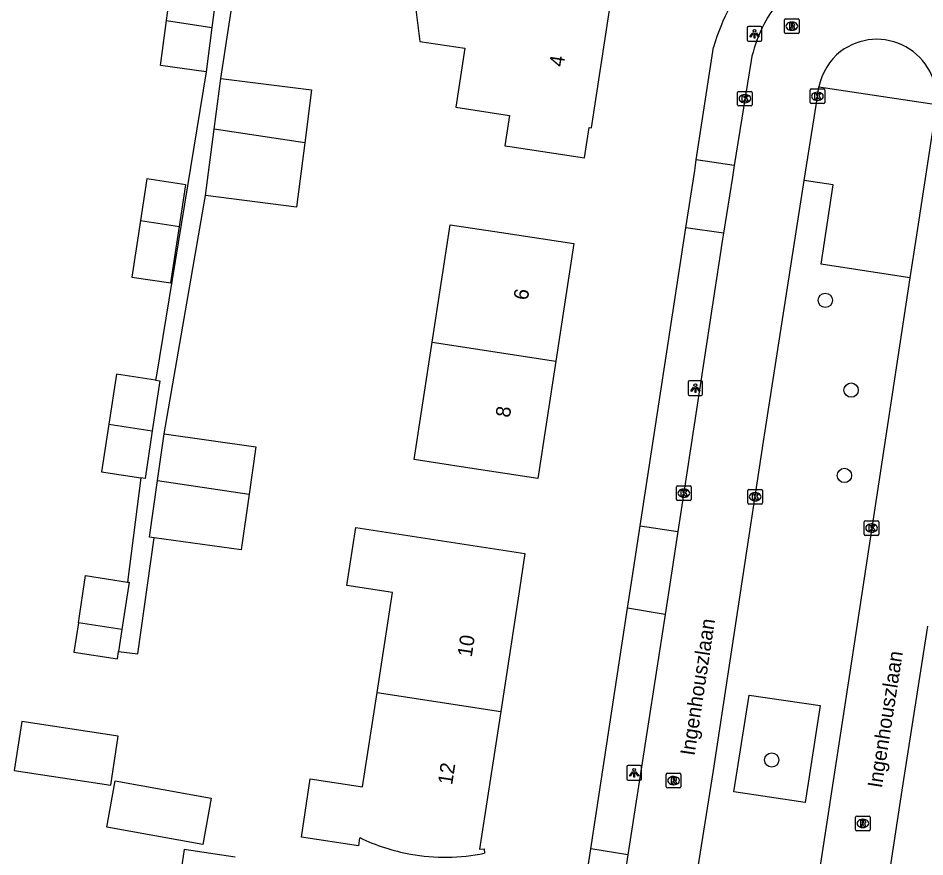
# Model space of a CAD drawing. Extents: x 161486 to 162249, y 379484 to 380829.
# Drawn here: x 162025.3 to 162087.4, y 380415.4 to 380472.8 of the extents above; entities that cross this region are included whole.
import ezdxf

# ---------------------------------------------------------------- set-up
doc = ezdxf.new("R2010")
doc.units = 0
for name, color, linetype in [('IMGEO_Boom', 7, 'Continuous'), ('IMGEO_Groenvoorziening', 7, 'Continuous'), ('IMGEO_Kolk', 7, 'Continuous'), ('IMGEO_Lichtpunt', 7, 'Continuous'), ('IMGEO_Openbare_ruimte_label', 7, 'Continuous'), ('IMGEO_Pand', 7, 'Continuous'), ('IMGEO_Pand_nummerreeks', 7, 'Continuous'), ('IMGEO_Rijbaan_lokaal_open', 7, 'Continuous'), ('IMGEO_Rioolput', 7, 'Continuous'), ('IMGEO_Voetpad_open', 7, 'Continuous')]:
    doc.layers.add(name, color=color, linetype=linetype)

msp = doc.modelspace()

# ---------------------------------------------------------------- linework, layer by layer
at = {"layer": 'IMGEO_Boom'}
for centre in [(162080.548, 380453.464), (162082.314, 380447.322), (162081.854, 380441.484), (162076.881, 380422.024)]:
    msp.add_circle(centre, 0.489, dxfattribs=at)
at = {"layer": 'IMGEO_Groenvoorziening'}
for points in [[(162086.334, 380454.996), (162080.254, 380455.927), (162081.091, 380461.363), (162079.109, 380461.669)], [(162074.286, 380419.839), (162075.344, 380426.462), (162080.192, 380425.742), (162079.172, 380419.106), (162074.286, 380419.839)]]:
    msp.add_lwpolyline(points, dxfattribs=at)
at = {"layer": 'IMGEO_Kolk'}
for p, q in [((162074.543, 380466.831), (162074.543, 380467.683)), ((162074.618, 380467.757), (162075.47, 380467.757)), ((162075.544, 380467.683), (162075.544, 380466.831)), ((162079.503, 380466.993), (162079.503, 380467.845)), ((162079.578, 380467.919), (162080.43, 380467.919)), ((162079.991, 380467.699), (162080.016, 380467.699)), ((162080.504, 380467.845), (162080.504, 380466.993)), ((162075.031, 380467.537), (162075.056, 380467.537)), ((162080.014, 380467.139), (162079.989, 380467.139)), ((162075.47, 380466.757), (162074.618, 380466.757)), ((162075.054, 380466.977), (162075.029, 380466.977)), ((162080.43, 380466.919), (162079.578, 380466.919)), ((162070.364, 380439.852), (162070.364, 380440.704)), ((162070.439, 380440.778), (162071.291, 380440.778)), ((162070.852, 380440.558), (162070.877, 380440.558)), ((162071.365, 380440.704), (162071.365, 380439.852)), ((162075.244, 380439.603), (162075.244, 380440.455)), ((162075.319, 380440.529), (162076.171, 380440.529)), ((162076.245, 380440.455), (162076.245, 380439.603)), ((162071.291, 380439.778), (162070.439, 380439.778)), ((162070.875, 380439.998), (162070.85, 380439.998)), ((162075.755, 380439.749), (162075.73, 380439.749)), ((162075.732, 380440.309), (162075.757, 380440.309)), ((162076.171, 380439.529), (162075.319, 380439.529)), ((162083.216, 380437.462), (162083.216, 380438.314)), ((162083.291, 380438.388), (162084.143, 380438.388)), ((162083.704, 380438.168), (162083.729, 380438.168)), ((162084.217, 380438.314), (162084.217, 380437.462)), ((162084.143, 380437.388), (162083.291, 380437.388)), ((162083.727, 380437.608), (162083.702, 380437.608))]:
    msp.add_line(p, q, dxfattribs=at)
for points in [[(162074.543, 380466.831), (162074.543, 380467.683)], [(162074.618, 380467.757), (162075.47, 380467.757)], [(162075.544, 380467.683), (162075.544, 380466.831)], [(162079.503, 380466.993), (162079.503, 380467.845)], [(162079.578, 380467.919), (162080.43, 380467.919)], [(162079.824, 380467.619), (162079.947, 380467.619), (162079.947, 380467.468), (162080.077, 380467.619), (162080.241, 380467.619), (162080.095, 380467.468), (162080.248, 380467.219), (162080.096, 380467.219), (162080.011, 380467.383), (162079.947, 380467.316), (162079.947, 380467.219), (162079.824, 380467.219), (162079.824, 380467.619)], [(162080.504, 380467.845), (162080.504, 380466.993)], [(162074.864, 380467.457), (162074.987, 380467.457), (162074.987, 380467.306), (162075.117, 380467.457), (162075.281, 380467.457), (162075.135, 380467.306), (162075.288, 380467.057), (162075.136, 380467.057), (162075.051, 380467.221), (162074.987, 380467.154), (162074.987, 380467.057), (162074.864, 380467.057), (162074.864, 380467.457)], [(162075.47, 380466.757), (162074.618, 380466.757)], [(162080.43, 380466.919), (162079.578, 380466.919)], [(162070.364, 380439.852), (162070.364, 380440.704)], [(162070.439, 380440.778), (162071.291, 380440.778)], [(162070.685, 380440.478), (162070.808, 380440.478), (162070.808, 380440.327), (162070.938, 380440.478), (162071.102, 380440.478), (162070.956, 380440.327), (162071.109, 380440.078), (162070.957, 380440.078), (162070.872, 380440.242), (162070.808, 380440.175), (162070.808, 380440.078), (162070.685, 380440.078), (162070.685, 380440.478)], [(162071.365, 380440.704), (162071.365, 380439.852)], [(162075.244, 380439.603), (162075.244, 380440.455)], [(162075.319, 380440.529), (162076.171, 380440.529)], [(162076.245, 380440.455), (162076.245, 380439.603)], [(162071.291, 380439.778), (162070.439, 380439.778)], [(162075.565, 380440.229), (162075.688, 380440.229), (162075.688, 380440.078), (162075.818, 380440.229), (162075.982, 380440.229), (162075.836, 380440.078), (162075.989, 380439.829), (162075.837, 380439.829), (162075.752, 380439.993), (162075.688, 380439.926), (162075.688, 380439.829), (162075.565, 380439.829), (162075.565, 380440.229)], [(162076.171, 380439.529), (162075.319, 380439.529)], [(162083.216, 380437.462), (162083.216, 380438.314)], [(162083.291, 380438.388), (162084.143, 380438.388)], [(162083.537, 380438.088), (162083.66, 380438.088), (162083.66, 380437.937), (162083.79, 380438.088), (162083.954, 380438.088), (162083.808, 380437.937), (162083.961, 380437.688), (162083.809, 380437.688), (162083.724, 380437.852), (162083.66, 380437.785), (162083.66, 380437.688), (162083.537, 380437.688), (162083.537, 380438.088)], [(162084.217, 380438.314), (162084.217, 380437.462)], [(162084.143, 380437.388), (162083.291, 380437.388)]]:
    msp.add_lwpolyline(points, dxfattribs=at)
for centre, start, end in [((162074.62, 380467.681), 91.55205, 178.44795), ((162074.62, 380467.681), 91.55205, 178.44795), ((162075.468, 380467.681), 1.55205, 88.44795), ((162075.468, 380467.681), 1.55205, 88.44795), ((162079.58, 380467.843), 91.55205, 178.44795), ((162079.58, 380467.843), 91.55205, 178.44795), ((162080.428, 380467.843), 1.55205, 88.44795), ((162080.428, 380467.843), 1.55205, 88.44795), ((162079.58, 380466.995), 181.55205, 268.44795), ((162079.58, 380466.995), 181.55205, 268.44795), ((162080.428, 380466.995), 271.55205, 358.44795), ((162080.428, 380466.995), 271.55205, 358.44795), ((162074.62, 380466.833), 181.55205, 268.44795), ((162074.62, 380466.833), 181.55205, 268.44795), ((162075.468, 380466.833), 271.55205, 358.44795), ((162075.468, 380466.833), 271.55205, 358.44795), ((162070.441, 380440.702), 91.55205, 178.44795), ((162070.441, 380440.702), 91.55205, 178.44795), ((162071.289, 380440.702), 1.55205, 88.44795), ((162071.289, 380440.702), 1.55205, 88.44795), ((162075.321, 380440.453), 91.55205, 178.44795), ((162075.321, 380440.453), 91.55205, 178.44795), ((162076.169, 380440.453), 1.55205, 88.44795), ((162076.169, 380440.453), 1.55205, 88.44795), ((162070.441, 380439.854), 181.55205, 268.44795), ((162070.441, 380439.854), 181.55205, 268.44795), ((162071.289, 380439.854), 271.55205, 358.44795), ((162071.289, 380439.854), 271.55205, 358.44795), ((162075.321, 380439.605), 181.55205, 268.44795), ((162075.321, 380439.605), 181.55205, 268.44795), ((162076.169, 380439.605), 271.55205, 358.44795), ((162076.169, 380439.605), 271.55205, 358.44795), ((162083.293, 380438.312), 91.55205, 178.44795), ((162083.293, 380438.312), 91.55205, 178.44795), ((162084.141, 380438.312), 1.55205, 88.44795), ((162084.141, 380438.312), 1.55205, 88.44795), ((162083.293, 380437.464), 181.55205, 268.44795), ((162083.293, 380437.464), 181.55205, 268.44795), ((162084.141, 380437.464), 271.55205, 358.44795), ((162084.141, 380437.464), 271.55205, 358.44795)]:
    msp.add_arc(centre, 0.0765, start, end, dxfattribs=at)
for centre, major_axis, ratio, start_param, end_param in [((162079.99, 380467.419), (-0.387, 0.002), 0.722429, 4.712389, 7.853982), ((162080.015, 380467.419), (-0.39, 0.002), 0.717154, 1.570796, 4.712389), ((162075.03, 380467.257), (-0.387, 0.002), 0.722429, 4.712389, 7.853982), ((162075.055, 380467.257), (-0.39, 0.002), 0.717154, 1.570796, 4.712389), ((162070.851, 380440.278), (-0.387, 0.002), 0.722429, 4.712389, 7.853982), ((162070.876, 380440.278), (-0.39, 0.002), 0.717154, 1.570796, 4.712389), ((162075.731, 380440.029), (-0.387, 0.002), 0.722429, 4.712389, 7.853982), ((162075.756, 380440.029), (-0.39, 0.002), 0.717154, 1.570796, 4.712389), ((162083.703, 380437.888), (-0.387, 0.002), 0.722429, 4.712389, 7.853982), ((162083.728, 380437.888), (-0.39, 0.002), 0.717154, 1.570796, 4.712389)]:
    msp.add_ellipse(centre, major_axis=major_axis, ratio=ratio, start_param=start_param, end_param=end_param, dxfattribs=at)
at = {"layer": 'IMGEO_Lichtpunt'}
for p, q in [((162075.203, 380472.098), (162075.203, 380471.291)), ((162075.203, 380472.098), (162075.203, 380471.291)), ((162076.105, 380472.193), (162075.297, 380472.193)), ((162076.105, 380472.193), (162075.297, 380472.193)), ((162076.199, 380471.291), (162076.199, 380472.098)), ((162076.199, 380471.291), (162076.199, 380472.098)), ((162075.297, 380471.197), (162076.105, 380471.197)), ((162075.297, 380471.197), (162076.105, 380471.197)), ((162071.154, 380447.864), (162071.154, 380447.057)), ((162071.154, 380447.864), (162071.154, 380447.057)), ((162072.056, 380447.959), (162071.248, 380447.959)), ((162072.056, 380447.959), (162071.248, 380447.959)), ((162072.15, 380447.057), (162072.15, 380447.864)), ((162072.15, 380447.057), (162072.15, 380447.864)), ((162071.248, 380446.963), (162072.056, 380446.963)), ((162071.248, 380446.963), (162072.056, 380446.963)), ((162066.967, 380421.548), (162066.967, 380420.741)), ((162066.967, 380421.548), (162066.967, 380420.741)), ((162067.869, 380421.643), (162067.061, 380421.643)), ((162067.869, 380421.643), (162067.061, 380421.643)), ((162067.963, 380420.741), (162067.963, 380421.548)), ((162067.963, 380420.741), (162067.963, 380421.548)), ((162067.061, 380420.647), (162067.869, 380420.647)), ((162067.061, 380420.647), (162067.869, 380420.647))]:
    msp.add_line(p, q, dxfattribs=at)
for points in [[(162075.577, 380471.762), (162075.616, 380471.734), (162075.428, 380471.472), (162075.39, 380471.499), (162075.577, 380471.762)], [(162075.679, 380471.714), (162075.726, 380471.714), (162075.726, 380471.392), (162075.679, 380471.392), (162075.679, 380471.714)], [(162075.789, 380471.734), (162075.827, 380471.761), (162076.014, 380471.499), (162075.975, 380471.471), (162075.789, 380471.734)], [(162071.528, 380447.528), (162071.567, 380447.5), (162071.379, 380447.238), (162071.341, 380447.265), (162071.528, 380447.528)], [(162071.63, 380447.48), (162071.677, 380447.48), (162071.677, 380447.158), (162071.63, 380447.158), (162071.63, 380447.48)], [(162071.74, 380447.5), (162071.778, 380447.527), (162071.965, 380447.265), (162071.926, 380447.237), (162071.74, 380447.5)], [(162067.341, 380421.212), (162067.38, 380421.184), (162067.192, 380420.922), (162067.154, 380420.949), (162067.341, 380421.212)], [(162067.443, 380421.164), (162067.49, 380421.164), (162067.49, 380420.842), (162067.443, 380420.842), (162067.443, 380421.164)], [(162067.553, 380421.184), (162067.591, 380421.211), (162067.778, 380420.949), (162067.739, 380420.921), (162067.553, 380421.184)]]:
    msp.add_lwpolyline(points, dxfattribs=at)
for centre in [(162075.702, 380471.896), (162071.653, 380447.662), (162067.466, 380421.346)]:
    msp.add_circle(centre, 0.0994, dxfattribs=at)
for centre, start, end in [((162075.297, 380472.098), 90, 180), ((162075.297, 380472.098), 90, 180), ((162076.105, 380472.098), 0, 90), ((162076.105, 380472.098), 0, 90), ((162075.297, 380471.291), 180, 270), ((162075.297, 380471.291), 180, 270), ((162076.105, 380471.291), 270, 0), ((162076.105, 380471.291), 270, 360), ((162071.248, 380447.864), 90, 180), ((162071.248, 380447.864), 90, 180), ((162072.056, 380447.864), 0, 90), ((162072.056, 380447.864), 0, 90), ((162071.248, 380447.057), 180, 270), ((162071.248, 380447.057), 180, 270), ((162072.056, 380447.057), 270, 0), ((162072.056, 380447.057), 270, 360), ((162067.061, 380421.548), 90, 180), ((162067.061, 380421.548), 90, 180), ((162067.869, 380421.548), 0, 90), ((162067.869, 380421.548), 0, 90), ((162067.061, 380420.741), 180, 270), ((162067.061, 380420.741), 180, 270), ((162067.869, 380420.741), 270, 0), ((162067.869, 380420.741), 270, 360)]:
    msp.add_arc(centre, 0.0946, start, end, dxfattribs=at)
at = {"layer": 'IMGEO_Pand'}
for points in [[(162035.461, 380472.596), (162035.933, 380476.135), (162039.053, 380475.719)], [(162039.053, 380475.719), (162038.574, 380472.119)], [(162057.421, 380474.6), (162053.993, 380475.125), (162052.273, 380475.388), (162052.804, 380471.178), (162055.87, 380470.71), (162055.254, 380466.675), (162058.941, 380466.112), (162058.624, 380464.037), (162059.118, 380463.961), (162064.06, 380463.205), (162064.377, 380465.279), (162064.545, 380465.254), (162065.78, 380473.32)], [(162038.171, 380469.102), (162035.05, 380469.518), (162035.461, 380472.596)], [(162035.461, 380472.596), (162038.574, 380472.119)], [(162038.574, 380472.119), (162038.171, 380469.102)], [(162038.733, 380465.178), (162039.182, 380468.642)], [(162039.182, 380468.642), (162045.384, 380467.857), (162044.927, 380464.247)], [(162038.142, 380460.624), (162038.733, 380465.178)], [(162044.927, 380464.247), (162038.733, 380465.178)], [(162044.927, 380464.247), (162044.369, 380459.836), (162038.142, 380460.624)], [(162036.345, 380458.507), (162036.782, 380461.361), (162034.119, 380461.768), (162033.682, 380458.914)], [(162033.682, 380458.914), (162033.092, 380455.057), (162035.754, 380454.65), (162036.345, 380458.507)], [(162033.682, 380458.914), (162036.345, 380458.507)], [(162053.641, 380450.606), (162054.871, 380458.639), (162058.393, 380458.1), (162063.335, 380457.343), (162062.105, 380449.31)], [(162062.105, 380449.31), (162060.875, 380441.275), (162055.933, 380442.032), (162052.41, 380442.571), (162053.641, 380450.606)], [(162053.641, 380450.606), (162062.105, 380449.31)], [(162034.717, 380448.001), (162032.039, 380448.411), (162031.515, 380444.987)], [(162034.717, 380448.001), (162035.018, 380447.955), (162034.494, 380444.531)], [(162031.515, 380444.987), (162031.017, 380441.736), (162033.708, 380441.324)], [(162031.515, 380444.987), (162034.494, 380444.531)], [(162034.494, 380444.531), (162033.997, 380441.28), (162033.708, 380441.324)], [(162034.847, 380441.152), (162035.293, 380444.33)], [(162035.293, 380444.33), (162041.567, 380443.449), (162041.112, 380440.21)], [(162034.627, 380437.222), (162034.302, 380437.268), (162034.847, 380441.152)], [(162034.847, 380441.152), (162041.112, 380440.21)], [(162041.112, 380440.21), (162040.576, 380436.387), (162034.627, 380437.222)], [(162049.873, 380426.629), (162050.922, 380433.478), (162047.805, 380433.956), (162048.412, 380437.923), (162059.989, 380436.151), (162059.567, 380433.393), (162058.333, 380425.335)], [(162029.434, 380431.396), (162029.93, 380434.632), (162032.806, 380434.192)], [(162032.806, 380434.192), (162032.909, 380434.176), (162032.414, 380430.94)], [(162029.434, 380431.396), (162029.13, 380429.41), (162032.11, 380428.954), (162032.187, 380429.454)], [(162032.414, 380430.94), (162029.434, 380431.396)], [(162032.414, 380430.94), (162032.187, 380429.454)], [(162048.682, 380416.711), (162048.596, 380416.149), (162044.693, 380416.747), (162045.303, 380420.735), (162048.886, 380420.186), (162049.873, 380426.629)], [(162049.873, 380426.629), (162058.333, 380425.335)], [(162058.333, 380425.335), (162056.893, 380415.926), (162057.207, 380415.941), (162057.222, 380415.641)], [(162025.043, 380421.306), (162031.65, 380420.293), (162032.164, 380423.65), (162025.557, 380424.662), (162025.043, 380421.306)], [(162031.383, 380417.424), (162031.955, 380420.597), (162038.514, 380419.415), (162037.941, 380416.242), (162031.383, 380417.424)], [(162040.155, 380415.383), (162036.677, 380415.907), (162035.714, 380409.527), (162039.193, 380409.002)]]:
    msp.add_lwpolyline(points, dxfattribs=at)
for centre, radius, start, end in [((162054.538, 380428.83), 13.459, 244.21022, 259.80309), ((162054.537, 380428.864), 13.493, 259.83291, 281.47872)]:
    msp.add_arc(centre, radius, start, end, dxfattribs=at)
at = {"layer": 'IMGEO_Rijbaan_lokaal_open'}
for points in [[(162075.462, 380469.878), (162074.316, 380462.681)], [(162079.109, 380461.669), (162079.934, 380466.953), (162080.1, 380468.066)], [(162088.161, 380466.855), (162086.762, 380457.785), (162086.334, 380454.996)], [(162074.316, 380462.681), (162074.19, 380461.892), (162073.58, 380458.062)], [(162068.281, 380392.494), (162068.301, 380392.631), (162068.936, 380396.33), (162069.473, 380399.828), (162072.897, 380421.316), (162076.318, 380443.8), (162079.109, 380461.669)], [(162073.58, 380458.062), (162073.515, 380457.652), (162070.871, 380440.312), (162070.46, 380437.662)], [(162086.334, 380454.996), (162084.564, 380443.452), (162082.313, 380428.629), (162079.94, 380413.167), (162078.243, 380402.6), (162077.729, 380399.561), (162077.34, 380396.967), (162076.646, 380392.468), (162075.971, 380388.219), (162075.628, 380385.97), (162075.199, 380383.16), (162074.906, 380381.422)], [(162070.46, 380437.662), (162069.9, 380434.06), (162069.578, 380431.982)], [(162069.578, 380431.982), (162068.55, 380425.36), (162067.04, 380415.543)], [(162084.667, 380412.462), (162085.816, 380419.971), (162087.553, 380431.171)], [(162067.04, 380415.543), (162066.343, 380411.007), (162065.773, 380407.399)]]:
    msp.add_lwpolyline(points, dxfattribs=at)
for centre, radius, start, end in [((162085.283, 380467.737), 10.051, 141.33868, 167.70024), ((162084.07, 380467.211), 4.106, 355.02498, 127.07644), ((162084.292, 380467.149), 4.291, 128.94292, 167.6653)]:
    msp.add_arc(centre, radius, start, end, dxfattribs=at)
at = {"layer": 'IMGEO_Rioolput'}
for p, q in [((162077.755, 380471.79), (162077.755, 380472.642)), ((162077.83, 380472.716), (162078.682, 380472.716)), ((162078.756, 380472.642), (162078.756, 380471.79)), ((162078.243, 380472.496), (162078.268, 380472.496)), ((162078.682, 380471.716), (162077.83, 380471.716)), ((162078.266, 380471.936), (162078.241, 380471.936)), ((162069.741, 380421.113), (162070.593, 380421.113)), ((162069.666, 380420.187), (162069.666, 380421.039)), ((162070.154, 380420.893), (162070.179, 380420.893)), ((162070.667, 380421.039), (162070.667, 380420.187)), ((162070.593, 380420.113), (162069.741, 380420.113)), ((162070.177, 380420.333), (162070.152, 380420.333)), ((162082.618, 380417.26), (162082.618, 380418.112)), ((162082.693, 380418.186), (162083.545, 380418.186)), ((162083.619, 380418.112), (162083.619, 380417.26)), ((162083.129, 380417.406), (162083.104, 380417.406)), ((162083.106, 380417.966), (162083.131, 380417.966)), ((162083.545, 380417.186), (162082.693, 380417.186))]:
    msp.add_line(p, q, dxfattribs=at)
for points in [[(162077.755, 380471.79), (162077.755, 380472.642)], [(162077.83, 380472.716), (162078.682, 380472.716)], [(162078.756, 380472.642), (162078.756, 380471.79)], [(162078.344, 380472.414), (162078.092, 380472.416), (162078.092, 380472.016)], [(162078.092, 380472.016), (162078.216, 380472.016), (162078.216, 380472.178), (162078.227, 380472.178)], [(162078.27, 380472.335), (162078.216, 380472.335), (162078.216, 380472.254)], [(162078.216, 380472.254), (162078.268, 380472.254)], [(162078.274, 380472.149), (162078.345, 380472.016), (162078.485, 380472.016), (162078.42, 380472.142)], [(162078.682, 380471.716), (162077.83, 380471.716)], [(162069.741, 380421.113), (162070.593, 380421.113)], [(162069.666, 380420.187), (162069.666, 380421.039)], [(162070.255, 380420.811), (162070.003, 380420.813), (162070.003, 380420.413)], [(162070.003, 380420.413), (162070.127, 380420.413), (162070.127, 380420.575), (162070.138, 380420.575)], [(162070.181, 380420.732), (162070.127, 380420.732), (162070.127, 380420.651)], [(162070.127, 380420.651), (162070.179, 380420.651)], [(162070.185, 380420.546), (162070.256, 380420.413), (162070.396, 380420.413), (162070.331, 380420.539)], [(162070.667, 380421.039), (162070.667, 380420.187)], [(162070.593, 380420.113), (162069.741, 380420.113)], [(162082.618, 380417.26), (162082.618, 380418.112)], [(162082.693, 380418.186), (162083.545, 380418.186)], [(162083.619, 380418.112), (162083.619, 380417.26)], [(162083.207, 380417.884), (162082.955, 380417.886), (162082.955, 380417.486)], [(162082.955, 380417.486), (162083.079, 380417.486), (162083.079, 380417.648), (162083.09, 380417.648)], [(162083.133, 380417.805), (162083.079, 380417.805), (162083.079, 380417.724)], [(162083.079, 380417.724), (162083.131, 380417.724)], [(162083.137, 380417.619), (162083.208, 380417.486), (162083.348, 380417.486), (162083.283, 380417.612)], [(162083.545, 380417.186), (162082.693, 380417.186)]]:
    msp.add_lwpolyline(points, dxfattribs=at)
for centre, radius, start, end in [((162077.832, 380472.64), 0.0765, 91.55205, 178.44795), ((162077.832, 380472.64), 0.0765, 91.55205, 178.44795), ((162078.68, 380472.64), 0.0765, 1.55205, 88.44795), ((162078.68, 380472.64), 0.0765, 1.55205, 88.44795), ((162078.226, 380472.125), 0.0533, 26.02933, 88.69889), ((162078.252, 380472.443), 0.19, 274.7715, 282.96867), ((162078.276, 380472.239), 0.0964, 77.00612, 93.18647), ((162078.29, 380472.296), 0.0378, 276.66336, 79.67722), ((162078.343, 380472.304), 0.109, 350.36119, 89.41601), ((162078.341, 380472.304), 0.112, 277.58423, 350.98172), ((162078.325, 380472.089), 0.108, 29.51342, 73.79051), ((162077.832, 380471.792), 0.0765, 181.55205, 268.44795), ((162077.832, 380471.792), 0.0765, 181.55205, 268.44795), ((162078.68, 380471.792), 0.0765, 271.55205, 358.44795), ((162078.68, 380471.792), 0.0765, 271.55205, 358.44795), ((162069.743, 380421.037), 0.0765, 91.55205, 178.44795), ((162069.743, 380421.037), 0.0765, 91.55205, 178.44795), ((162070.591, 380421.037), 0.0765, 1.55205, 88.44795), ((162070.591, 380421.037), 0.0765, 1.55205, 88.44795), ((162070.137, 380420.522), 0.0533, 26.02933, 88.69889), ((162070.163, 380420.84), 0.19, 274.7715, 282.96867), ((162070.187, 380420.636), 0.0964, 77.00612, 93.18647), ((162070.201, 380420.693), 0.0378, 276.66336, 79.67722), ((162070.254, 380420.701), 0.109, 350.36119, 89.41601), ((162070.252, 380420.701), 0.112, 277.58423, 350.98172), ((162070.236, 380420.486), 0.108, 29.51342, 73.79051), ((162069.743, 380420.189), 0.0765, 181.55205, 268.44795), ((162069.743, 380420.189), 0.0765, 181.55205, 268.44795), ((162070.591, 380420.189), 0.0765, 271.55205, 358.44795), ((162070.591, 380420.189), 0.0765, 271.55205, 358.44795), ((162082.695, 380418.11), 0.0765, 91.55205, 178.44795), ((162082.695, 380418.11), 0.0765, 91.55205, 178.44795), ((162083.543, 380418.11), 0.0765, 1.55205, 88.44795), ((162083.543, 380418.11), 0.0765, 1.55205, 88.44795), ((162083.089, 380417.595), 0.0533, 26.02933, 88.69889), ((162083.115, 380417.913), 0.19, 274.7715, 282.96867), ((162083.139, 380417.709), 0.0964, 77.00612, 93.18647), ((162083.153, 380417.766), 0.0378, 276.66336, 79.67722), ((162083.206, 380417.774), 0.109, 350.36119, 89.41601), ((162083.204, 380417.774), 0.112, 277.58423, 350.98172), ((162083.188, 380417.559), 0.108, 29.51342, 73.79051), ((162082.695, 380417.262), 0.0765, 181.55205, 268.44795), ((162082.695, 380417.262), 0.0765, 181.55205, 268.44795), ((162083.543, 380417.262), 0.0765, 271.55205, 358.44795), ((162083.543, 380417.262), 0.0765, 271.55205, 358.44795)]:
    msp.add_arc(centre, radius, start, end, dxfattribs=at)
for centre, major_axis, ratio, start_param, end_param in [((162078.242, 380472.216), (-0.387, 0.002), 0.722429, 4.712389, 7.853982), ((162078.267, 380472.216), (-0.39, 0.002), 0.717154, 1.570796, 4.712389), ((162070.153, 380420.613), (-0.387, 0.002), 0.722429, 4.712389, 7.853982), ((162070.178, 380420.613), (-0.39, 0.002), 0.717154, 1.570796, 4.712389), ((162083.105, 380417.686), (-0.387, 0.002), 0.722429, 4.712389, 7.853982), ((162083.13, 380417.686), (-0.39, 0.002), 0.717154, 1.570796, 4.712389)]:
    msp.add_ellipse(centre, major_axis=major_axis, ratio=ratio, start_param=start_param, end_param=end_param, dxfattribs=at)
at = {"layer": 'IMGEO_Voetpad_open'}
for points in [[(162039.182, 380468.642), (162042.32, 380489.168), (162042.401, 380489.155)], [(162071.717, 380463.064), (162072.9, 380470.783)], [(162038.171, 380469.102), (162034.769, 380448.343), (162034.717, 380448.001)], [(162080.1, 380468.066), (162088.161, 380466.855)], [(162071.006, 380458.43), (162071.607, 380462.347), (162071.717, 380463.064)], [(162074.316, 380462.681), (162071.717, 380463.064)], [(162035.293, 380444.33), (162038.142, 380460.624)], [(162067.88, 380438.039), (162071.006, 380458.43)], [(162073.58, 380458.062), (162071.006, 380458.43)], [(162033.708, 380441.324), (162032.806, 380434.192)], [(162067.019, 380432.417), (162067.331, 380434.452), (162067.88, 380438.039)], [(162067.88, 380438.039), (162070.46, 380437.662)], [(162032.187, 380429.454), (162033.513, 380429.287), (162034.627, 380437.222)], [(162064.494, 380415.945), (162067.019, 380432.417)], [(162069.578, 380431.982), (162067.019, 380432.417)], [(162063.237, 380407.751), (162064.494, 380415.945)], [(162067.04, 380415.543), (162064.494, 380415.945)]]:
    msp.add_lwpolyline(points, dxfattribs=at)
msp.add_arc((162088.934, 380465.934), 16.751, 142.62521, 163.17257, dxfattribs=at)

# ---------------------------------------------------------------- texts
at = {"layer": 'IMGEO_Openbare_ruimte_label'}
for rotation, p in [(81.37577, (162071.593, 380422.28)), (81.1972, (162084.413, 380420.067))]:
    msp.add_text('Ingenhouszlaan', height=1, rotation=rotation, dxfattribs=at).set_placement(p)
at = {"layer": 'IMGEO_Pand_nummerreeks'}
for s, rotation, p in [('4', 81.29698, (162062.63, 380469.397)), ('6', 81.29564, (162060.187, 380453.436)), ('8', 81.29564, (162058.957, 380445.406)), ('10', 81.28643, (162056.348, 380429.021)), ('12', 81.30271, (162055.01, 380420.282))]:
    msp.add_text(s, height=1, rotation=rotation, dxfattribs=at).set_placement(p)

doc.saveas('drawing.dxf')
